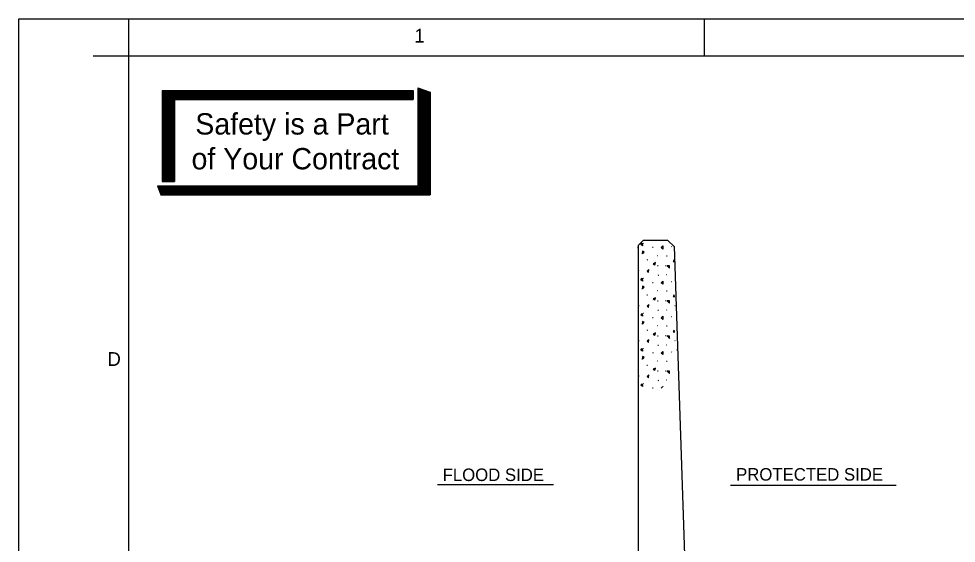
# Model space of a CAD drawing. Extents: x 44742.55 to 44745.38, y 44738.95 to 44741.13.
# Drawn here: x 44742.553 to 44743.373, y 44740.673 to 44741.132 of the extents above; entities that cross this region are included whole.
import ezdxf

# ---------------------------------------------------------------- set-up
doc = ezdxf.new("R2010")
doc.units = 0
for name, color, linetype in [('G-ANNO-PATT', 7, 'Continuous'), ('Level 1', 7, 'Continuous'), ('Level 10', 7, 'Continuous'), ('Level 9', 7, 'Continuous')]:
    doc.layers.add(name, color=color, linetype=linetype)

msp = doc.modelspace()

# ---------------------------------------------------------------- linework, layer by layer
at = {"layer": 'G-ANNO-PATT'}
for p, q in [((44743.09949, 44740.93569), (44743.09913, 44740.93591)), ((44743.09808, 44740.92672), (44743.09777, 44740.92674)), ((44743.10767, 44740.93204), (44743.10733, 44740.93201)), ((44743.11162, 44740.92489), (44743.11131, 44740.92494)), ((44743.10277, 44740.92121), (44743.1024, 44740.92102)), ((44743.12002, 44740.92462), (44743.1196, 44740.92462)), ((44743.09551, 44740.9118), (44743.0951, 44740.91187)), ((44743.11212, 44740.91602), (44743.1117, 44740.91602)), ((44743.11912, 44740.91617), (44743.11872, 44740.91617)), ((44743.12674, 44740.91186), (44743.12667, 44740.91187)), ((44743.09949, 44740.90495), (44743.09913, 44740.90516)), ((44743.10767, 44740.9013), (44743.10733, 44740.90127)), ((44743.11245, 44740.90784), (44743.11203, 44740.90773)), ((44743.11974, 44740.90827), (44743.11943, 44740.90815)), ((44743.12424, 44740.90205), (44743.12391, 44740.9022)), ((44743.09808, 44740.89598), (44743.09777, 44740.896)), ((44743.11162, 44740.89415), (44743.11131, 44740.8942)), ((44743.12002, 44740.89388), (44743.1196, 44740.89388)), ((44743.10277, 44740.89047), (44743.1024, 44740.89028)), ((44743.11212, 44740.88528), (44743.1117, 44740.88528)), ((44743.11912, 44740.88543), (44743.11872, 44740.88543)), ((44743.09551, 44740.88106), (44743.0951, 44740.88113)), ((44743.11245, 44740.8771), (44743.11203, 44740.87698)), ((44743.11974, 44740.87752), (44743.11943, 44740.87741)), ((44743.12707, 44740.88106), (44743.12667, 44740.88113)), ((44743.09949, 44740.87421), (44743.09913, 44740.87442)), ((44743.10767, 44740.87055), (44743.10733, 44740.87052)), ((44743.12424, 44740.8713), (44743.12391, 44740.87146)), ((44743.09808, 44740.86523), (44743.09777, 44740.86526)), ((44743.10277, 44740.85973), (44743.1024, 44740.85954)), ((44743.11162, 44740.86341), (44743.11131, 44740.86346)), ((44743.12002, 44740.86314), (44743.1196, 44740.86314)), ((44743.11212, 44740.85454), (44743.1117, 44740.85454)), ((44743.11912, 44740.85469), (44743.11872, 44740.85469)), ((44743.09551, 44740.85032), (44743.0951, 44740.85039)), ((44743.09949, 44740.84347), (44743.09913, 44740.84368)), ((44743.11245, 44740.84636), (44743.11203, 44740.84624)), ((44743.11974, 44740.84678), (44743.11943, 44740.84666)), ((44743.12707, 44740.85032), (44743.12667, 44740.85039)), ((44743.10767, 44740.83981), (44743.10733, 44740.83978)), ((44743.12424, 44740.84056), (44743.12391, 44740.84072)), ((44743.09808, 44740.83449), (44743.09777, 44740.83452)), ((44743.10277, 44740.82898), (44743.1024, 44740.8288)), ((44743.11162, 44740.83266), (44743.11131, 44740.83272)), ((44743.12002, 44740.8324), (44743.1196, 44740.8324)), ((44743.09551, 44740.81958), (44743.0951, 44740.81965)), ((44743.11212, 44740.8238), (44743.1117, 44740.8238)), ((44743.11912, 44740.82394), (44743.11872, 44740.82394)), ((44743.09949, 44740.81273), (44743.09913, 44740.81294)), ((44743.11245, 44740.81562), (44743.11203, 44740.8155)), ((44743.11974, 44740.81604), (44743.11943, 44740.81592)), ((44743.10767, 44740.80907), (44743.10733, 44740.80904))]:
    msp.add_line(p, q, dxfattribs=at)
for points in [[(44743.09838, 44740.93348), (44743.09688, 44740.93462), (44743.09831, 44740.93589)], [(44743.11612, 44740.93066), (44743.11467, 44740.932), (44743.11627, 44740.93343)], [(44743.09853, 44740.92661), (44743.09987, 44740.92811), (44743.09838, 44740.92891)], [(44743.10917, 44740.91694), (44743.10991, 44740.91885), (44743.10784, 44740.91784)], [(44743.12634, 44740.91962), (44743.12612, 44740.92134), (44743.12516, 44740.91991)], [(44743.10404, 44740.91293), (44743.10244, 44740.91153), (44743.10377, 44740.91041)], [(44743.12205, 44740.91607), (44743.12017, 44740.91617), (44743.1222, 44740.91409)], [(44743.09838, 44740.90274), (44743.09688, 44740.90387), (44743.09831, 44740.90515)], [(44743.11612, 44740.89992), (44743.11467, 44740.90126), (44743.11627, 44740.90269)], [(44743.09853, 44740.89587), (44743.09987, 44740.89737), (44743.09838, 44740.89816)], [(44743.10917, 44740.88619), (44743.10991, 44740.88811), (44743.10784, 44740.8871)], [(44743.12205, 44740.88533), (44743.12017, 44740.88543), (44743.1222, 44740.88335)], [(44743.12634, 44740.88888), (44743.12612, 44740.89059), (44743.12516, 44740.88916)], [(44743.10404, 44740.88219), (44743.10244, 44740.88079), (44743.10377, 44740.87967)], [(44743.09838, 44740.872), (44743.09688, 44740.87313), (44743.09831, 44740.87441)], [(44743.11612, 44740.86918), (44743.11467, 44740.87052), (44743.11627, 44740.87194)], [(44743.09853, 44740.86512), (44743.09987, 44740.86662), (44743.09838, 44740.86742)], [(44743.12634, 44740.85814), (44743.12612, 44740.85985), (44743.12516, 44740.85842)], [(44743.10404, 44740.85144), (44743.10244, 44740.85005), (44743.10377, 44740.84893)], [(44743.10917, 44740.85545), (44743.10991, 44740.85737), (44743.10784, 44740.85636)], [(44743.12205, 44740.85459), (44743.12017, 44740.85469), (44743.1222, 44740.85261)], [(44743.09838, 44740.84126), (44743.09688, 44740.84239), (44743.09831, 44740.84366)], [(44743.09853, 44740.83438), (44743.09987, 44740.83588), (44743.09838, 44740.83668)], [(44743.11612, 44740.83844), (44743.11467, 44740.83977), (44743.11627, 44740.8412)], [(44743.10917, 44740.82471), (44743.10991, 44740.82662), (44743.10784, 44740.82562)], [(44743.10404, 44740.8207), (44743.10244, 44740.8193), (44743.10377, 44740.81819)], [(44743.12205, 44740.82384), (44743.12017, 44740.82394), (44743.1222, 44740.82187)], [(44743.09838, 44740.81052), (44743.09688, 44740.81165), (44743.09831, 44740.81292)]]:
    msp.add_lwpolyline(points, close=True, dxfattribs=at)
for points in [[(44743.09477, 44740.93165), (44743.09463, 44740.93281)], [(44743.09463, 44740.91966), (44743.09477, 44740.91962)], [(44743.09477, 44740.88888), (44743.09477, 44740.88897)], [(44743.12866, 44740.84223), (44743.12844, 44740.84239), (44743.12865, 44740.84258)], [(44743.11473, 44740.80898), (44743.11467, 44740.80903), (44743.11627, 44740.81046), (44743.11626, 44740.81019)]]:
    msp.add_lwpolyline(points, dxfattribs=at)
at = {"layer": 'Level 1'}
msp.add_line((44743.12424, 44740.93279), (44743.12391, 44740.93294), dxfattribs=at)
msp.add_lwpolyline([(44742.55302, 44741.13232), (44745.38041, 44741.13232), (44745.38041, 44738.94702), (44742.55302, 44738.94702)], close=True, dxfattribs=at)
at = {"layer": 'Level 10'}
for p, q in [((44742.64941, 44741.09993), (44742.64941, 44741.13232)), ((44743.1527, 44741.09993), (44743.1527, 44741.13232)), ((44742.61803, 44741.09993), (44742.64907, 44741.09993)), ((44742.67847, 44741.06956), (44742.89804, 44741.06956)), ((44742.67847, 44741.06956), (44742.67847, 44740.98982)), ((44742.67847, 44741.06854), (44742.89804, 44741.06854)), ((44742.67847, 44741.06757), (44742.89804, 44741.06757)), ((44742.67847, 44741.06654), (44742.89804, 44741.06654)), ((44742.67847, 44741.06552), (44742.89804, 44741.06552)), ((44742.67847, 44741.06455), (44742.89804, 44741.06455)), ((44742.6795, 44741.06956), (44742.6795, 44740.98982)), ((44742.68046, 44741.06956), (44742.68046, 44740.98982)), ((44742.68149, 44741.06956), (44742.68149, 44740.98982)), ((44742.68245, 44741.06956), (44742.68245, 44740.98982)), ((44742.68348, 44741.06956), (44742.68348, 44740.98982)), ((44742.68451, 44741.06956), (44742.68451, 44740.98982)), ((44742.68547, 44741.06956), (44742.68547, 44740.98982)), ((44742.6865, 44741.06956), (44742.6865, 44740.98982)), ((44742.68753, 44741.06956), (44742.68753, 44740.98982)), ((44742.68849, 44741.06956), (44742.68849, 44740.98982)), ((44742.89804, 44741.06956), (44742.89804, 44741.06153)), ((44742.90209, 44741.07194), (44742.90209, 44740.98622)), ((44742.90209, 44741.07194), (44742.91282, 44741.06796)), ((44742.90279, 44741.07168), (44742.90279, 44740.97819)), ((44742.90376, 44741.0713), (44742.90376, 44740.97819)), ((44742.90479, 44741.07091), (44742.90479, 44740.97819)), ((44742.90581, 44741.07053), (44742.90581, 44740.97819)), ((44742.90678, 44741.07021), (44742.90678, 44740.97819)), ((44742.90781, 44741.06982), (44742.90781, 44740.97819)), ((44742.90877, 44741.06944), (44742.90877, 44740.97819)), ((44742.9098, 44741.06905), (44742.9098, 44740.97819)), ((44742.91083, 44741.06873), (44742.91083, 44740.97819)), ((44742.91179, 44741.06796), (44742.91179, 44740.97819)), ((44742.91282, 44741.06796), (44742.91282, 44740.97819)), ((44742.67847, 44741.06352), (44742.89804, 44741.06352)), ((44742.67847, 44741.06256), (44742.89804, 44741.06256)), ((44742.6892, 44741.06153), (44742.89804, 44741.06153)), ((44742.6892, 44741.06153), (44742.6892, 44740.98982)), ((44742.67442, 44740.98622), (44742.90209, 44740.98622)), ((44742.67442, 44740.98622), (44742.67738, 44740.97819)), ((44742.67481, 44740.98519), (44742.90279, 44740.98519)), ((44742.67513, 44740.98423), (44742.90279, 44740.98423)), ((44742.67551, 44740.9832), (44742.90279, 44740.9832)), ((44742.67847, 44740.98982), (44742.6892, 44740.98982)), ((44742.6759, 44740.98217), (44742.90279, 44740.98217)), ((44742.67628, 44740.98121), (44742.90279, 44740.98121)), ((44742.67667, 44740.98018), (44742.90279, 44740.98018)), ((44742.67699, 44740.97922), (44742.90279, 44740.97922)), ((44742.67738, 44740.97819), (44742.91282, 44740.97819)), ((44743.09915, 44740.9383), (44743.09457, 44740.93372)), ((44743.09457, 44740.93372), (44743.09457, 44740.46722)), ((44743.12074, 44740.9383), (44743.09915, 44740.9383)), ((44743.12074, 44740.9383), (44743.12616, 44740.93288)), ((44743.12616, 44740.93288), (44743.14168, 44740.46722)), ((44742.91909, 44740.72468), (44743.02055, 44740.72468)), ((44743.17537, 44740.72402), (44743.32017, 44740.72402))]:
    msp.add_line(p, q, dxfattribs=at)
at = {"layer": 'Level 9'}
for p, q in [((44742.64941, 44738.97941), (44742.64941, 44741.09993)), ((44742.64941, 44741.09993), (44745.17144, 44741.09993))]:
    msp.add_line(p, q, dxfattribs=at)

# ---------------------------------------------------------------- texts
at = {"layer": 'Level 1'}
for s, p in [('1', (44742.89901, 44741.1115)), ('D', (44742.63067, 44740.82851))]:
    msp.add_text(s, height=0.01203, dxfattribs=at).set_placement(p)
at = {"layer": 'Level 10'}
for s, height, p in [('Safety is a Part', 0.018659, (44742.70739, 44741.03096)), ('of Your Contract', 0.018659, (44742.70412, 44741.00051)), ('FLOOD SIDE', 0.010945, (44742.9237, 44740.72773)), ('PROTECTED SIDE', 0.0109453, (44743.18033, 44740.72809))]:
    msp.add_text(s, height=height, dxfattribs=at).set_placement(p)

doc.saveas('drawing.dxf')
